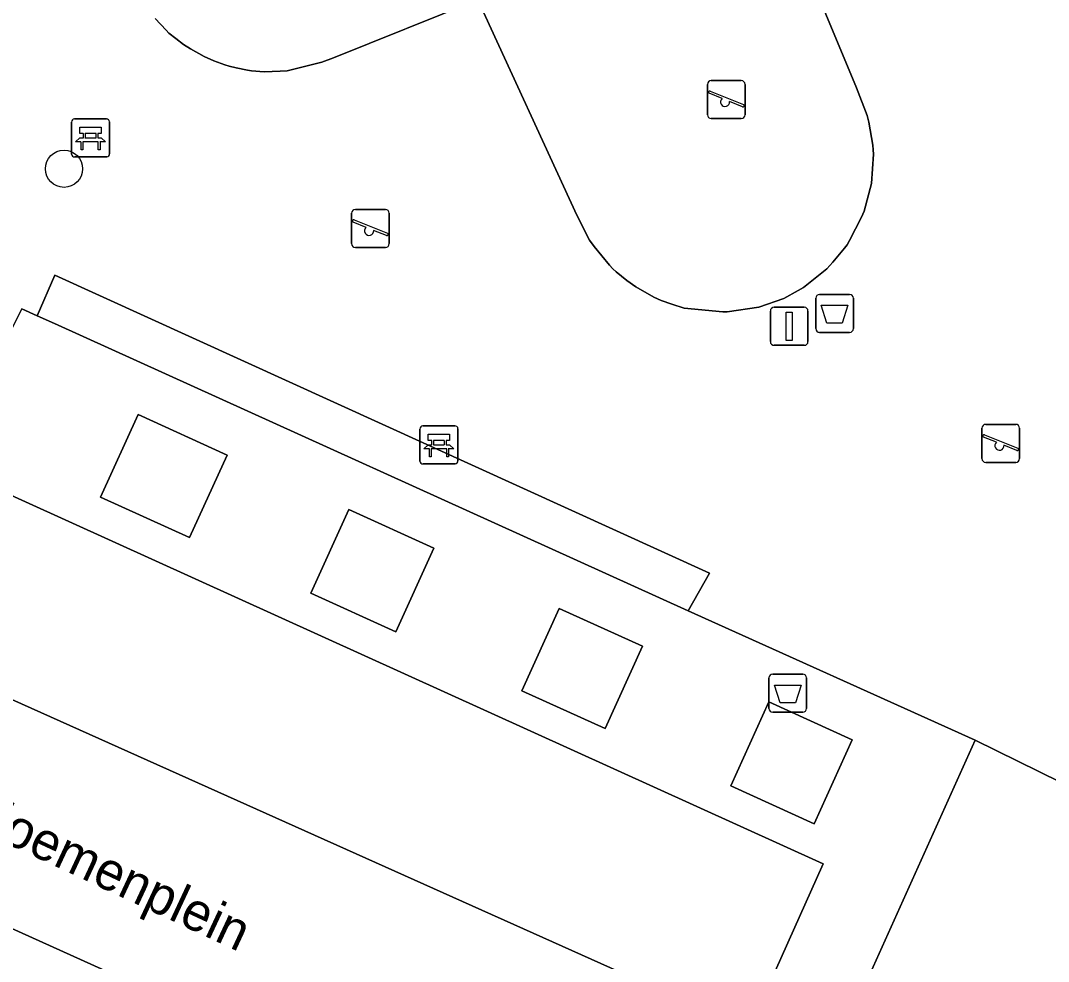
# Model space of a CAD drawing. Extents: x 161838 to 162344, y 381620 to 382160.
# Drawn here: x 162173.63 to 162200.67, y 381697.89 to 381722.64 of the extents above; entities that cross this region are included whole.
import ezdxf

# ---------------------------------------------------------------- set-up
doc = ezdxf.new("R2010")
doc.units = 0
for name, color, linetype in [('IMGEO_Afvalbak', 7, 'Continuous'), ('IMGEO_Bank', 7, 'Continuous'), ('IMGEO_Boom', 7, 'Continuous'), ('IMGEO_Groenvoorziening', 7, 'Continuous'), ('IMGEO_Haag', 7, 'Continuous'), ('IMGEO_Lichtmast', 7, 'Continuous'), ('IMGEO_Openbare_ruimte_label', 7, 'Continuous'), ('IMGEO_Parkeervlak_open', 7, 'Continuous'), ('IMGEO_Rijbaan_lokaal_open', 7, 'Continuous'), ('IMGEO_Speelvoorziening', 7, 'Continuous'), ('IMGEO_Terreindeel_zand', 7, 'Continuous'), ('IMGEO_Voetpad_open', 7, 'Continuous')]:
    doc.layers.add(name, color=color, linetype=linetype)

msp = doc.modelspace()

# ---------------------------------------------------------------- linework, layer by layer
at = {"layer": 'IMGEO_Afvalbak'}
for p, q in [((162194.552, 381714.534), (162194.552, 381715.334)), ((162194.552, 381715.334), (162194.552, 381714.534)), ((162194.652, 381715.434), (162195.442, 381715.434)), ((162195.442, 381715.434), (162194.652, 381715.434)), ((162195.542, 381715.334), (162195.542, 381714.534)), ((162195.542, 381714.534), (162195.542, 381715.334)), ((162195.442, 381714.434), (162194.652, 381714.434)), ((162194.652, 381714.434), (162195.442, 381714.434)), ((162193.32, 381704.544), (162193.32, 381705.344)), ((162193.32, 381705.344), (162193.32, 381704.544)), ((162193.42, 381705.444), (162194.21, 381705.444)), ((162194.21, 381705.444), (162193.42, 381705.444)), ((162194.31, 381705.344), (162194.31, 381704.544)), ((162194.31, 381704.544), (162194.31, 381705.344)), ((162194.21, 381704.444), (162193.42, 381704.444)), ((162193.42, 381704.444), (162194.21, 381704.444))]:
    msp.add_line(p, q, dxfattribs=at)
for points in [[(162194.695, 381715.148), (162195.399, 381715.148), (162195.25, 381714.678), (162194.844, 381714.678), (162194.695, 381715.148)], [(162193.463, 381705.158), (162194.167, 381705.158), (162194.018, 381704.688), (162193.612, 381704.688), (162193.463, 381705.158)]]:
    msp.add_lwpolyline(points, dxfattribs=at)
for centre, start, end in [((162194.652, 381715.334), 90, 180), ((162194.652, 381715.334), 90, 180), ((162195.442, 381715.334), 0, 90), ((162195.442, 381715.334), 360, 90), ((162194.652, 381714.534), 180, 270), ((162194.652, 381714.534), 180, 270), ((162195.442, 381714.534), 270, 0), ((162195.442, 381714.534), 270, 0), ((162193.42, 381705.344), 90, 180), ((162193.42, 381705.344), 90, 180), ((162194.21, 381705.344), 0, 90), ((162194.21, 381705.344), 360, 90), ((162193.42, 381704.544), 180, 270), ((162193.42, 381704.544), 180, 270), ((162194.21, 381704.544), 270, 0), ((162194.21, 381704.544), 270, 0)]:
    msp.add_arc(centre, 0.1, start, end, dxfattribs=at)
at = {"layer": 'IMGEO_Bank'}
for p, q in [((162174.975, 381719.124), (162174.975, 381719.965)), ((162174.975, 381719.965), (162174.975, 381719.124)), ((162175.05, 381720.049), (162175.891, 381720.049)), ((162175.891, 381720.049), (162175.05, 381720.049)), ((162175.975, 381719.974), (162175.975, 381719.133)), ((162175.975, 381719.133), (162175.975, 381719.974)), ((162175.284, 381719.555), (162175.284, 381719.661)), ((162175.328, 381719.661), (162175.328, 381719.555)), ((162175.616, 381719.667), (162175.334, 381719.667)), ((162175.622, 381719.555), (162175.622, 381719.661)), ((162175.666, 381719.661), (162175.666, 381719.555)), ((162175.672, 381719.447), (162175.279, 381719.447)), ((162175.334, 381719.549), (162175.616, 381719.549)), ((162175.9, 381719.049), (162175.059, 381719.049)), ((162175.059, 381719.049), (162175.9, 381719.049)), ((162184.139, 381711.051), (162184.139, 381711.892)), ((162184.139, 381711.892), (162184.139, 381711.051)), ((162184.214, 381711.976), (162185.055, 381711.976)), ((162185.055, 381711.976), (162184.214, 381711.976)), ((162185.139, 381711.901), (162185.139, 381711.06)), ((162185.139, 381711.06), (162185.139, 381711.901)), ((162184.448, 381711.482), (162184.448, 381711.588)), ((162184.492, 381711.588), (162184.492, 381711.482)), ((162184.78, 381711.594), (162184.498, 381711.594)), ((162184.498, 381711.476), (162184.78, 381711.476)), ((162184.786, 381711.482), (162184.786, 381711.588)), ((162184.83, 381711.588), (162184.83, 381711.482)), ((162184.836, 381711.374), (162184.443, 381711.374)), ((162185.064, 381710.976), (162184.223, 381710.976)), ((162184.223, 381710.976), (162185.064, 381710.976))]:
    msp.add_line(p, q, dxfattribs=at)
for points in [[(162175.278, 381719.667), (162175.192, 381719.667), (162175.192, 381719.828), (162175.755, 381719.828), (162175.755, 381719.667), (162175.672, 381719.667)], [(162175.222, 381719.447), (162175.08, 381719.447), (162175.192, 381719.549), (162175.278, 381719.549)], [(162175.272, 381719.44), (162175.272, 381719.233), (162175.229, 381719.233), (162175.229, 381719.44)], [(162175.672, 381719.549), (162175.755, 381719.549), (162175.867, 381719.447), (162175.728, 381719.447)], [(162175.722, 381719.44), (162175.722, 381719.233), (162175.678, 381719.233), (162175.678, 381719.44)], [(162184.442, 381711.594), (162184.356, 381711.594), (162184.356, 381711.755), (162184.919, 381711.755), (162184.919, 381711.594), (162184.836, 381711.594)], [(162184.386, 381711.374), (162184.244, 381711.374), (162184.356, 381711.476), (162184.442, 381711.476)], [(162184.836, 381711.476), (162184.919, 381711.476), (162185.031, 381711.374), (162184.892, 381711.374)], [(162184.436, 381711.367), (162184.436, 381711.16), (162184.393, 381711.16), (162184.393, 381711.367)], [(162184.886, 381711.367), (162184.886, 381711.16), (162184.842, 381711.16), (162184.842, 381711.367)]]:
    msp.add_lwpolyline(points, dxfattribs=at)
for centre, radius, start, end in [((162175.053, 381719.971), 0.0779, 92.4484, 184.2845), ((162175.053, 381719.971), 0.0779, 92.4484, 184.2845), ((162175.897, 381719.971), 0.0779, 2.4484, 94.2845), ((162175.897, 381719.971), 0.0779, 2.4484, 94.2845), ((162175.277, 381719.66), 0.00671, 2.8957, 87.1043), ((162175.334, 381719.66), 0.00671, 92.8957, 177.1043), ((162175.616, 381719.66), 0.00671, 2.8957, 87.1043), ((162175.673, 381719.66), 0.00671, 92.8957, 177.1043), ((162175.222, 381719.44), 0.00671, 2.8957, 87.1043), ((162175.279, 381719.44), 0.00671, 92.8957, 177.1043), ((162175.277, 381719.556), 0.00671, 272.8957, 357.1043), ((162175.334, 381719.556), 0.00671, 182.8957, 267.1043), ((162175.616, 381719.556), 0.00671, 272.8957, 357.1043), ((162175.673, 381719.556), 0.00671, 182.8957, 267.1043), ((162175.671, 381719.44), 0.00671, 2.8957, 87.1043), ((162175.728, 381719.44), 0.00671, 92.8957, 177.1043), ((162175.053, 381719.127), 0.0779, 182.4484, 274.2845), ((162175.053, 381719.127), 0.0779, 182.4484, 274.2845), ((162175.897, 381719.127), 0.0779, 272.4484, 4.2845), ((162175.897, 381719.127), 0.0779, 272.4484, 4.2845), ((162184.217, 381711.898), 0.0779, 92.4484, 184.2845), ((162184.217, 381711.898), 0.0779, 92.4484, 184.2845), ((162185.061, 381711.898), 0.0779, 2.4484, 94.2845), ((162185.061, 381711.898), 0.0779, 2.4484, 94.2845), ((162184.441, 381711.587), 0.00671, 2.8957, 87.1043), ((162184.441, 381711.483), 0.00671, 272.8957, 357.1043), ((162184.498, 381711.587), 0.00671, 92.8957, 177.1043), ((162184.498, 381711.483), 0.00671, 182.8957, 267.1043), ((162184.78, 381711.587), 0.00671, 2.8957, 87.1043), ((162184.78, 381711.483), 0.00671, 272.8957, 357.1043), ((162184.837, 381711.587), 0.00671, 92.8957, 177.1043), ((162184.837, 381711.483), 0.00671, 182.8957, 267.1043), ((162184.386, 381711.367), 0.00671, 2.8957, 87.1043), ((162184.443, 381711.367), 0.00671, 92.8957, 177.1043), ((162184.835, 381711.367), 0.00671, 2.8957, 87.1043), ((162184.892, 381711.367), 0.00671, 92.8957, 177.1043), ((162184.217, 381711.054), 0.0779, 182.4484, 274.2845), ((162184.217, 381711.054), 0.0779, 182.4484, 274.2845), ((162185.061, 381711.054), 0.0779, 272.4484, 4.2845), ((162185.061, 381711.054), 0.0779, 272.4484, 4.2845)]:
    msp.add_arc(centre, radius, start, end, dxfattribs=at)
at = {"layer": 'IMGEO_Boom'}
msp.add_circle((162174.776, 381718.738), 0.489, dxfattribs=at)
at = {"layer": 'IMGEO_Groenvoorziening'}
for points in [[(162192.541, 381728.271), (162195.625, 381720.87), (162195.908, 381720.142), (162195.949, 381719.967), (162196.049, 381719.362), (162196.058, 381719.239), (162196.067, 381719.123), (162196.022, 381718.354), (162195.829, 381717.627), (162195.757, 381717.463), (162195.44, 381716.852), (162195.378, 381716.734), (162195.309, 381716.652), (162195.002, 381716.281), (162194.843, 381716.106), (162194.231, 381715.617), (162194.09, 381715.538), (162193.709, 381715.326), (162193.057, 381715.096), (162192.219, 381714.977), (162192.106, 381714.975), (162191.092, 381715.075), (162190.766, 381715.176), (162190.481, 381715.272), (162190.388, 381715.318), (162190.294, 381715.365), (162189.816, 381715.63), (162189.577, 381715.803), (162189.304, 381716.027), (162189.211, 381716.103), (162189.128, 381716.204), (162188.724, 381716.694), (162188.603, 381716.863), (162188.265, 381717.518), (162185.66, 381723.193), (162181.867, 381721.657), (162181.555, 381721.54), (162180.65, 381721.315), (162180.464, 381721.306), (162180.045, 381721.291), (162179.709, 381721.315), (162179.605, 381721.336), (162179.304, 381721.396), (162179.118, 381721.433), (162179.009, 381721.473), (162178.717, 381721.58), (162178.458, 381721.693), (162178.107, 381721.891), (162177.918, 381722.01), (162177.713, 381722.166), (162177.532, 381722.309), (162177.46, 381722.387), (162177.177, 381722.693)], [(162173.385, 381714.496), (162173.667, 381715.053), (162174.065, 381714.873), (162174.538, 381715.935), (162191.752, 381708.101), (162191.198, 381707.111), (162198.743, 381703.712), (162200.989, 381702.599), (162201.889, 381700.486), (162203.137, 381698.864), (162206.127, 381698.125)], [(162206.127, 381698.125), (162203.137, 381698.864), (162201.889, 381700.486), (162200.989, 381702.599), (162198.743, 381703.712), (162195.428, 381696.339), (162194.952, 381695.269), (162206.336, 381690.092)]]:
    msp.add_lwpolyline(points, dxfattribs=at)
for points in [[(162174.538, 381715.935), (162174.065, 381714.873), (162174.526, 381714.664), (162191.198, 381707.111), (162191.752, 381708.101)], [(162178.079, 381709.036), (162179.064, 381711.208), (162176.722, 381712.271), (162175.737, 381710.098)], [(162183.508, 381706.558), (162184.506, 381708.759), (162182.268, 381709.774), (162181.27, 381707.574)], [(162189.01, 381704.011), (162189.994, 381706.18), (162187.802, 381707.174), (162186.818, 381705.005)], [(162194.51, 381701.507), (162195.513, 381703.717), (162193.315, 381704.714), (162192.313, 381702.504)]]:
    msp.add_lwpolyline(points, close=True, dxfattribs=at)
at = {"layer": 'IMGEO_Haag'}
msp.add_lwpolyline([(162174.065, 381714.873), (162174.526, 381714.664), (162191.198, 381707.111), (162191.752, 381708.101), (162174.538, 381715.935)], close=True, dxfattribs=at)
at = {"layer": 'IMGEO_Lichtmast'}
for p, q in [((162193.357, 381714.194), (162193.357, 381714.994)), ((162193.357, 381714.994), (162193.357, 381714.194)), ((162193.457, 381715.094), (162194.247, 381715.094)), ((162194.247, 381715.094), (162193.457, 381715.094)), ((162194.347, 381714.994), (162194.347, 381714.194)), ((162194.347, 381714.194), (162194.347, 381714.994)), ((162194.247, 381714.094), (162193.457, 381714.094)), ((162193.457, 381714.094), (162194.247, 381714.094))]:
    msp.add_line(p, q, dxfattribs=at)
msp.add_lwpolyline([(162193.777, 381714.969), (162193.927, 381714.969), (162193.927, 381714.219), (162193.777, 381714.219), (162193.777, 381714.969)], dxfattribs=at)
for centre, start, end in [((162193.457, 381714.994), 90, 180), ((162193.457, 381714.994), 90, 180), ((162194.247, 381714.994), 0, 90), ((162194.247, 381714.994), 360, 90), ((162193.457, 381714.194), 180, 270), ((162193.457, 381714.194), 180, 270), ((162194.247, 381714.194), 270, 0), ((162194.247, 381714.194), 270, 0)]:
    msp.add_arc(centre, 0.1, start, end, dxfattribs=at)
at = {"layer": 'IMGEO_Parkeervlak_open'}
msp.add_lwpolyline([(162172.71, 381710.455), (162170.848, 381706.126), (162170.775, 381705.955), (162192.789, 381696.092), (162192.884, 381696.303), (162194.748, 381700.457)], close=True, dxfattribs=at)
at = {"layer": 'IMGEO_Rijbaan_lokaal_open'}
msp.add_lwpolyline([(162168.836, 381701.751), (162168.498, 381700.961), (162190.513, 381691.034), (162190.876, 381691.811), (162192.206, 381691.211), (162192.992, 381692.935), (162193.752, 381694.6), (162192.389, 381695.213), (162192.789, 381696.092), (162170.775, 381705.955), (162170.425, 381705.076), (162168.827, 381705.791), (162168.089, 381704.089), (162167.365, 381702.42)], close=True, dxfattribs=at)
at = {"layer": 'IMGEO_Speelvoorziening'}
for p, q in [((162191.702, 381720.158), (162191.702, 381720.958)), ((162191.702, 381720.958), (162191.702, 381720.158)), ((162191.802, 381721.058), (162192.592, 381721.058)), ((162192.592, 381721.058), (162191.802, 381721.058)), ((162192.692, 381720.958), (162192.692, 381720.158)), ((162192.692, 381720.158), (162192.692, 381720.958)), ((162192.085, 381720.586), (162191.746, 381720.723)), ((162191.771, 381720.783), (162192.647, 381720.43)), ((162192.623, 381720.37), (162192.283, 381720.507)), ((162192.592, 381720.058), (162191.802, 381720.058)), ((162191.802, 381720.058), (162192.592, 381720.058)), ((162182.44, 381717.668), (162183.23, 381717.668)), ((162183.23, 381717.668), (162182.44, 381717.668)), ((162182.34, 381716.768), (162182.34, 381717.568)), ((162182.34, 381717.568), (162182.34, 381716.768)), ((162183.33, 381717.568), (162183.33, 381716.768)), ((162183.33, 381716.768), (162183.33, 381717.568)), ((162182.723, 381717.196), (162182.384, 381717.333)), ((162182.409, 381717.393), (162183.285, 381717.04)), ((162183.261, 381716.98), (162182.921, 381717.117)), ((162183.23, 381716.668), (162182.44, 381716.668)), ((162182.44, 381716.668), (162183.23, 381716.668)), ((162199.022, 381712.015), (162199.812, 381712.015)), ((162199.812, 381712.015), (162199.022, 381712.015)), ((162198.922, 381711.115), (162198.922, 381711.915)), ((162198.922, 381711.915), (162198.922, 381711.115)), ((162198.991, 381711.74), (162199.867, 381711.387)), ((162199.912, 381711.915), (162199.912, 381711.115)), ((162199.912, 381711.115), (162199.912, 381711.915)), ((162199.305, 381711.543), (162198.966, 381711.68)), ((162199.843, 381711.327), (162199.503, 381711.464)), ((162199.812, 381711.015), (162199.022, 381711.015)), ((162199.022, 381711.015), (162199.812, 381711.015))]:
    msp.add_line(p, q, dxfattribs=at)
for centre, radius, start, end in [((162191.802, 381720.958), 0.1, 90, 180), ((162191.802, 381720.958), 0.1, 90, 180), ((162192.592, 381720.958), 0.1, 0, 90), ((162192.592, 381720.958), 0.1, 360, 90), ((162191.759, 381720.753), 0.0327, 68.078, 248.078), ((162192.164, 381720.496), 0.12, 130.9928, 5.1632), ((162192.635, 381720.4), 0.0327, 248.078, 68.078), ((162191.802, 381720.158), 0.1, 180, 270), ((162191.802, 381720.158), 0.1, 180, 270), ((162192.592, 381720.158), 0.1, 270, 0), ((162192.592, 381720.158), 0.1, 270, 0), ((162182.44, 381717.568), 0.1, 90, 180), ((162182.44, 381717.568), 0.1, 90, 180), ((162183.23, 381717.568), 0.1, 0, 90), ((162183.23, 381717.568), 0.1, 360, 90), ((162182.397, 381717.363), 0.0327, 68.078, 248.078), ((162182.802, 381717.106), 0.12, 130.9928, 5.1632), ((162183.273, 381717.01), 0.0327, 248.078, 68.078), ((162182.44, 381716.768), 0.1, 180, 270), ((162182.44, 381716.768), 0.1, 180, 270), ((162183.23, 381716.768), 0.1, 270, 0), ((162183.23, 381716.768), 0.1, 270, 0), ((162199.022, 381711.915), 0.1, 90, 180), ((162199.022, 381711.915), 0.1, 90, 180), ((162199.812, 381711.915), 0.1, 0, 90), ((162199.812, 381711.915), 0.1, 360, 90), ((162198.979, 381711.71), 0.0327, 68.078, 248.078), ((162199.384, 381711.453), 0.12, 130.9928, 5.1632), ((162199.855, 381711.357), 0.0327, 248.078, 68.078), ((162199.022, 381711.115), 0.1, 180, 270), ((162199.022, 381711.115), 0.1, 180, 270), ((162199.812, 381711.115), 0.1, 270, 0), ((162199.812, 381711.115), 0.1, 270, 0)]:
    msp.add_arc(centre, radius, start, end, dxfattribs=at)
at = {"layer": 'IMGEO_Terreindeel_zand'}
msp.add_lwpolyline([(162177.177, 381722.693), (162177.46, 381722.387), (162177.532, 381722.309), (162177.713, 381722.166), (162177.918, 381722.01), (162178.107, 381721.891), (162178.458, 381721.693), (162178.717, 381721.58), (162179.009, 381721.473), (162179.118, 381721.433), (162179.304, 381721.396), (162179.605, 381721.336), (162179.709, 381721.315), (162180.045, 381721.291), (162180.464, 381721.306), (162180.65, 381721.315), (162181.555, 381721.54), (162181.867, 381721.657), (162185.66, 381723.193), (162188.265, 381717.518), (162188.603, 381716.863), (162188.724, 381716.694), (162189.128, 381716.204), (162189.211, 381716.103), (162189.304, 381716.027), (162189.577, 381715.803), (162189.816, 381715.63), (162190.294, 381715.365), (162190.388, 381715.318), (162190.481, 381715.272), (162190.766, 381715.176), (162191.092, 381715.075), (162192.106, 381714.975), (162192.219, 381714.977), (162193.057, 381715.096), (162193.709, 381715.326), (162194.09, 381715.538), (162194.231, 381715.617), (162194.843, 381716.106), (162195.002, 381716.281), (162195.309, 381716.652), (162195.378, 381716.734), (162195.44, 381716.852), (162195.757, 381717.463), (162195.829, 381717.627), (162196.022, 381718.354), (162196.067, 381719.123), (162196.058, 381719.239), (162196.049, 381719.362), (162195.949, 381719.967), (162195.908, 381720.142), (162195.625, 381720.87), (162192.541, 381728.271)], dxfattribs=at)
at = {"layer": 'IMGEO_Voetpad_open'}
for points in [[(162174.526, 381714.664), (162174.065, 381714.873), (162173.667, 381715.053), (162173.385, 381714.496), (162170.977, 381715.518), (162169.768, 381712.761), (162169.514, 381712.181), (162171.984, 381711.132), (162170.37, 381707.654), (162169.339, 381708.142), (162168.826, 381707.033), (162170.848, 381706.126), (162172.71, 381710.455), (162194.748, 381700.457), (162192.884, 381696.303), (162194.952, 381695.269), (162195.428, 381696.339), (162198.743, 381703.712), (162191.198, 381707.111)], [(162175.737, 381710.098), (162176.722, 381712.271), (162179.064, 381711.208), (162178.079, 381709.036)], [(162182.268, 381709.774), (162184.506, 381708.759), (162183.508, 381706.558), (162181.27, 381707.574)], [(162187.802, 381707.174), (162189.994, 381706.18), (162189.01, 381704.011), (162186.818, 381705.005)], [(162193.315, 381704.714), (162195.513, 381703.717), (162194.51, 381701.507), (162192.313, 381702.504)]]:
    msp.add_lwpolyline(points, close=True, dxfattribs=at)
msp.add_lwpolyline([(162207.784, 381684.172), (162194.402, 381690.217), (162192.206, 381691.211), (162190.876, 381691.811), (162190.513, 381691.034), (162168.498, 381700.961)], dxfattribs=at)

# ---------------------------------------------------------------- texts
at = {"layer": 'IMGEO_Openbare_ruimte_label'}
msp.add_text('Bloemenplein', height=1, rotation=334.9727, dxfattribs=at).set_placement((162172.032, 381701.564))

doc.saveas('drawing.dxf')
